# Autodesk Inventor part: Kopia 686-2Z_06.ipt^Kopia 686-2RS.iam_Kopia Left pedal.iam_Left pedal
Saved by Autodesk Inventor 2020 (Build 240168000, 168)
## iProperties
Created: 2017-10
Part Number: Kopia 686-2Z_06.ipt^Kopia 686-2RS.iam_Kopia Left pedal.iam_Left pedal
Material: Ogólny
Document SubType Name: Modeling
Designer: Tomasz
Density: 1 g/cm^3
Appearance: Domyślna
Sending System: SolidWorks 2017
Last Author: Tomasz
Last Saved: 2017-10-01
Author: Tomasz
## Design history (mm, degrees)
